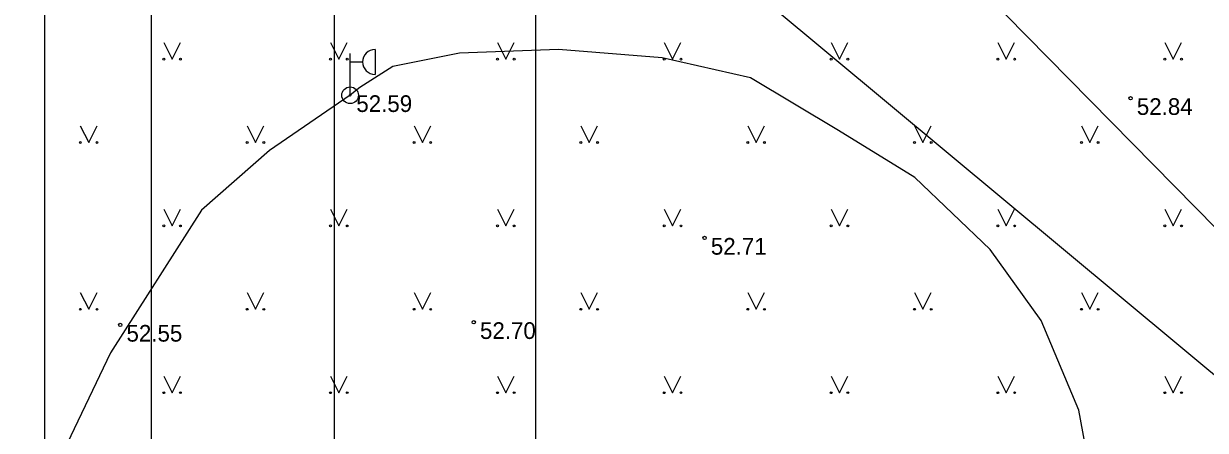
# Model space of a CAD drawing. Extents: x 619806 to 620082, y 405176 to 405386.
# Drawn here: x 619933.05 to 619968.46, y 405321.37 to 405333.56 of the extents above; entities that cross this region are included whole.
import ezdxf

# ---------------------------------------------------------------- set-up
doc = ezdxf.new("R2010")
doc.units = 0
for name, color, linetype in [('APGS_ELEM_####_####_#', 7, 'Continuous'), ('APGS_VADP_ZSPR_####_I', 7, 'Continuous'), ('RAMI_PLAN_####_TKST_#', 7, 'Continuous'), ('RELJ_AATZ_####_TKST_#', 7, 'Continuous'), ('RELJ_ELEM_####_####_#', 7, 'Continuous'), ('RELJ_HORZ_PAMT_####_#', 7, 'Continuous'), ('SAKT_VADP_KABE_####_#', 7, 'Continuous'), ('TERT_ELEM_####_####_#', 7, 'Continuous'), ('UDTK_VADP_UDEN_####_#', 7, 'Continuous')]:
    doc.layers.add(name, color=color, linetype=linetype)

msp = doc.modelspace()

# ---------------------------------------------------------------- linework, layer by layer
at = {"layer": 'APGS_ELEM_####_####_#'}
for p, q in [((619942.835, 405331.416), (619942.835, 405332.666)), ((619943.585, 405332.791), (619943.585, 405332.041)), ((619942.835, 405332.416), (619943.21, 405332.416))]:
    msp.add_line(p, q, dxfattribs=at)
for radius in [0.25, 0.0225]:
    msp.add_circle((619942.835, 405331.416), radius, dxfattribs=at)
msp.add_arc((619943.585, 405332.416), 0.375, 90, 270, dxfattribs=at)
at = {"layer": 'APGS_VADP_ZSPR_####_I'}
msp.add_lwpolyline([(619965.238, 405318.885), (619964.67, 405321.977), (619963.546, 405324.666), (619962.02, 405326.796), (619959.755, 405328.956), (619957.47, 405330.364), (619954.831, 405331.943), (619952.182, 405332.537), (619949.084, 405332.789), (619946.112, 405332.683), (619944.118, 405332.282), (619943.13, 405331.653), (619942.835, 405331.416), (619940.418, 405329.761), (619938.384, 405327.969), (619935.65, 405323.694), (619934.135, 405320.515)], dxfattribs=at)
at = {"layer": 'RAMI_PLAN_####_TKST_#'}
msp.add_line((619942.357, 405361.716), (619942.357, 405215.404), dxfattribs=at)
for points in [[(619933.685, 405385.595), (620082.185, 405385.595), (620082.185, 405175.595), (619933.685, 405175.595)], [(619805.793, 405180.095), (619805.793, 405373.209), (619948.393, 405373.209), (619948.393, 405180.095)], [(619936.885, 405180.095), (619936.885, 405373.209), (620079.485, 405373.209), (620079.485, 405180.095)]]:
    msp.add_lwpolyline(points, close=True, dxfattribs=at)
at = {"layer": 'RELJ_ELEM_####_####_#'}
for centre in [(619966.225, 405331.328), (619953.459, 405327.138), (619935.947, 405324.531), (619946.541, 405324.611)]:
    msp.add_circle(centre, 0.05, dxfattribs=at)
at = {"layer": 'RELJ_HORZ_PAMT_####_#'}
msp.add_spline([(619981.917, 405331.06), (619983.458, 405327.733), (619983.458, 405326.44), (619981.371, 405324.921), (619975.066, 405321.914), (619973.572, 405320.043), (619972.785, 405317.322), (619969.353, 405316.166), (619966.558, 405315.51), (619964.797, 405313.519), (619963.449, 405310.459), (619961.207, 405309.682), (619957.576, 405309.593), (619955.503, 405308.248), (619954.267, 405303.638), (619953.77, 405299.801), (619953.847, 405298.296), (619954.537, 405297.798), (619956.258, 405297.458), (619956.781, 405297.091)], degree=3, dxfattribs=at)
at = {"layer": 'SAKT_VADP_KABE_####_#'}
msp.add_lwpolyline([(619935.629, 405357.201), (619939.538, 405347.363), (619973.032, 405319.457), (620006.975, 405291.595), (620036.262, 405267.248), (620043.553, 405261.241)], dxfattribs=at)
at = {"layer": 'TERT_ELEM_####_####_#'}
for p, q in [((619937.25, 405333), (619937.5, 405332.5)), ((619937.5, 405332.5), (619937.75, 405333)), ((619942.25, 405333), (619942.5, 405332.5)), ((619942.5, 405332.5), (619942.75, 405333)), ((619947.25, 405333), (619947.5, 405332.5)), ((619947.5, 405332.5), (619947.75, 405333)), ((619952.25, 405333), (619952.5, 405332.5)), ((619952.5, 405332.5), (619952.75, 405333)), ((619957.25, 405333), (619957.5, 405332.5)), ((619957.5, 405332.5), (619957.75, 405333)), ((619962.25, 405333), (619962.5, 405332.5)), ((619962.5, 405332.5), (619962.75, 405333)), ((619967.25, 405333), (619967.5, 405332.5)), ((619967.5, 405332.5), (619967.75, 405333)), ((619934.75, 405330.5), (619935, 405330)), ((619935, 405330), (619935.25, 405330.5)), ((619939.75, 405330.5), (619940, 405330)), ((619940, 405330), (619940.25, 405330.5)), ((619944.75, 405330.5), (619945, 405330)), ((619945, 405330), (619945.25, 405330.5)), ((619949.75, 405330.5), (619950, 405330)), ((619950, 405330), (619950.25, 405330.5)), ((619954.75, 405330.5), (619955, 405330)), ((619955, 405330), (619955.25, 405330.5)), ((619959.75, 405330.5), (619960, 405330)), ((619960, 405330), (619960.25, 405330.5)), ((619964.75, 405330.5), (619965, 405330)), ((619965, 405330), (619965.25, 405330.5)), ((619937.25, 405328), (619937.5, 405327.5)), ((619937.5, 405327.5), (619937.75, 405328)), ((619942.25, 405328), (619942.5, 405327.5)), ((619942.5, 405327.5), (619942.75, 405328)), ((619947.25, 405328), (619947.5, 405327.5)), ((619947.5, 405327.5), (619947.75, 405328)), ((619952.25, 405328), (619952.5, 405327.5)), ((619952.5, 405327.5), (619952.75, 405328)), ((619957.25, 405328), (619957.5, 405327.5)), ((619957.5, 405327.5), (619957.75, 405328)), ((619962.25, 405328), (619962.5, 405327.5)), ((619962.5, 405327.5), (619962.75, 405328)), ((619967.25, 405328), (619967.5, 405327.5)), ((619967.5, 405327.5), (619967.75, 405328)), ((619934.75, 405325.5), (619935, 405325)), ((619935, 405325), (619935.25, 405325.5)), ((619939.75, 405325.5), (619940, 405325)), ((619940, 405325), (619940.25, 405325.5)), ((619944.75, 405325.5), (619945, 405325)), ((619945, 405325), (619945.25, 405325.5)), ((619949.75, 405325.5), (619950, 405325)), ((619950, 405325), (619950.25, 405325.5)), ((619954.75, 405325.5), (619955, 405325)), ((619955, 405325), (619955.25, 405325.5)), ((619959.75, 405325.5), (619960, 405325)), ((619960, 405325), (619960.25, 405325.5)), ((619964.75, 405325.5), (619965, 405325)), ((619965, 405325), (619965.25, 405325.5)), ((619937.25, 405323), (619937.5, 405322.5)), ((619937.5, 405322.5), (619937.75, 405323)), ((619942.25, 405323), (619942.5, 405322.5)), ((619942.5, 405322.5), (619942.75, 405323)), ((619947.25, 405323), (619947.5, 405322.5)), ((619947.5, 405322.5), (619947.75, 405323)), ((619952.25, 405323), (619952.5, 405322.5)), ((619952.5, 405322.5), (619952.75, 405323)), ((619957.25, 405323), (619957.5, 405322.5)), ((619957.5, 405322.5), (619957.75, 405323)), ((619962.25, 405323), (619962.5, 405322.5)), ((619962.5, 405322.5), (619962.75, 405323)), ((619967.25, 405323), (619967.5, 405322.5)), ((619967.5, 405322.5), (619967.75, 405323))]:
    msp.add_line(p, q, dxfattribs=at)
for centre, radius in [((619937.25, 405332.5), 0.028), ((619937.75, 405332.5), 0.0263), ((619942.25, 405332.5), 0.028), ((619942.75, 405332.5), 0.0263), ((619947.25, 405332.5), 0.028), ((619947.75, 405332.5), 0.0263), ((619952.25, 405332.5), 0.028), ((619952.75, 405332.5), 0.0263), ((619957.25, 405332.5), 0.028), ((619957.75, 405332.5), 0.0263), ((619962.25, 405332.5), 0.028), ((619962.75, 405332.5), 0.0263), ((619967.25, 405332.5), 0.028), ((619967.75, 405332.5), 0.0263), ((619934.75, 405330), 0.028), ((619935.25, 405330), 0.0263), ((619939.75, 405330), 0.028), ((619940.25, 405330), 0.0263), ((619944.75, 405330), 0.028), ((619945.25, 405330), 0.0263), ((619949.75, 405330), 0.028), ((619950.25, 405330), 0.0263), ((619954.75, 405330), 0.028), ((619955.25, 405330), 0.0263), ((619959.75, 405330), 0.028), ((619960.25, 405330), 0.0263), ((619964.75, 405330), 0.028), ((619965.25, 405330), 0.0263), ((619937.25, 405327.5), 0.028), ((619937.75, 405327.5), 0.0263), ((619942.25, 405327.5), 0.028), ((619942.75, 405327.5), 0.0263), ((619947.25, 405327.5), 0.028), ((619947.75, 405327.5), 0.0263), ((619952.25, 405327.5), 0.028), ((619952.75, 405327.5), 0.0263), ((619957.25, 405327.5), 0.028), ((619957.75, 405327.5), 0.0263), ((619962.25, 405327.5), 0.028), ((619962.75, 405327.5), 0.0263), ((619967.25, 405327.5), 0.028), ((619967.75, 405327.5), 0.0263), ((619934.75, 405325), 0.028), ((619935.25, 405325), 0.0263), ((619939.75, 405325), 0.028), ((619940.25, 405325), 0.0263), ((619944.75, 405325), 0.028), ((619945.25, 405325), 0.0263), ((619949.75, 405325), 0.028), ((619950.25, 405325), 0.0263), ((619954.75, 405325), 0.028), ((619955.25, 405325), 0.0263), ((619959.75, 405325), 0.028), ((619960.25, 405325), 0.0263), ((619964.75, 405325), 0.028), ((619965.25, 405325), 0.0263), ((619937.25, 405322.5), 0.028), ((619937.75, 405322.5), 0.0263), ((619942.25, 405322.5), 0.028), ((619942.75, 405322.5), 0.0263), ((619947.25, 405322.5), 0.028), ((619947.75, 405322.5), 0.0263), ((619952.25, 405322.5), 0.028), ((619952.75, 405322.5), 0.0263), ((619957.25, 405322.5), 0.028), ((619957.75, 405322.5), 0.0263), ((619962.25, 405322.5), 0.028), ((619962.75, 405322.5), 0.0263), ((619967.25, 405322.5), 0.028), ((619967.75, 405322.5), 0.0263)]:
    msp.add_circle(centre, radius, dxfattribs=at)
at = {"layer": 'UDTK_VADP_UDEN_####_#'}
msp.add_lwpolyline([(619945.834, 405355.555), (619951.504, 405344.209), (619959.966, 405336.395), (619975.103, 405321.007), (620000.001, 405300.143)], dxfattribs=at)

# ---------------------------------------------------------------- texts
at = {"layer": 'RELJ_AATZ_####_TKST_#'}
for s, p in [(' 52.59', (619942.835, 405330.916)), (' 52.84', (619966.225, 405330.828)), (' 52.71', (619953.459, 405326.638)), (' 52.55', (619935.947, 405324.031)), (' 52.70', (619946.541, 405324.111))]:
    msp.add_text(s, height=0.5, dxfattribs=at).set_placement(p)

doc.saveas('drawing.dxf')
